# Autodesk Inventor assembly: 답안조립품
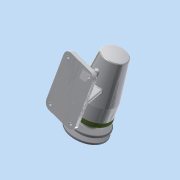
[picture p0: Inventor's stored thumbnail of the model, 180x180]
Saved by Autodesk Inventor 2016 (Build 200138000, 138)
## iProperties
Created: 2018-09
Part Number: 답안조립품
Material: 일반
Document SubType Name: Assembly
Designer: 605-07
Author: 605-07
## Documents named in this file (12)
- C:\Users\605-07\Desktop\답안조립품.iam
- C:\Users\605-07\Desktop\본체.ipt
- C:\Users\605-07\Desktop\480907V1011\V벨트풀리.ipt
- C:\Users\605-07\Desktop\480907V1011\멈춤나사 M3.ipt
- C:\Users\605-07\Desktop\480907V1011\베어링 6004.ipt
- C:\Users\605-07\Desktop\480907V1011\베어링 51202.ipt
- C:\Users\605-07\Desktop\480907V1011\볼트 M4.ipt
- C:\Users\605-07\Desktop\480907V1011\어댑터슬리브.ipt
- C:\Users\605-07\Desktop\480907V1011\오일 실.ipt
- C:\Users\605-07\Desktop\480907V1011\축.ipt
- C:\Users\605-07\Desktop\480907V1011\커버.ipt
- C:\Users\605-07\Desktop\480907V1011\키 5 x 5 x 16.ipt
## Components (1 placed, 1 different names)
1. V벨트풀리:1 — 각도:2
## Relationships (1: Angle 1)
- 각도:2 [Angle]: V벨트풀리:1
